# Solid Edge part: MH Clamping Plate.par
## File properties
Author: Dan
Template: metric part.par
Last saved by: Dan
Revision: 18
Application: Solid Edge
Density: 7833.000 kg/m^3
Accuracy: 0.990
Material: Steel
Face Style: Steel
Fill Style: ANSI32(Steel)
Virtual Style: Machined steel
Coef. of Thermal Exp: 1.3e-05
Thermal Conductivity: 32.0
Specific Heat: 481.0
Modulus of Elasticity: 199947953000.0
Poisson's Ratio: 0.29
Yield Stress: 262000766.0
Ultimate Stress: 358527364.0
Elongation: 0.0
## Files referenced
..\Moving Half.asm
C:\Drawing Files Other\Dave\Tente\HUP 125X36H45-TSA 02-07-2011\Wheel Mould\MH Die Plate.par
ZC:\Drawing Files Other\Dave\Tente\HUP 125X36H45-TSA 02-07-2011\Wheel Mould\Moving Half.asm
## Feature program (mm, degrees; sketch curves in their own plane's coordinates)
sketch for "unnamed Protrusion 1" plane through (0, 0, 0) normal (0, 0, 1) x-axis (1, 0, 0)
extrude "unnamed Protrusion 1" add finite 26 along -normal
sketch for "Hole_9" plane through (0, 0, -26) normal (0, 0, -1) x-axis (1, 0, 0)
  hole centre (-170, 116) bore radius 8.25
hole "Hole_9" diameter 16.5 through  CounterBoreDepth = 17 mm
sketch for "unnamed Hole 1" plane through (0, 0, -26) normal (0, 0, -1) x-axis (1, 0, 0)
hole "unnamed Hole 1" through
sketch for "unnamed Hole 2" plane through (0, 0, -26) normal (0, 0, -1) x-axis (1, 0, 0)
  hole centre (170, -116) bore radius 8.25
hole "unnamed Hole 2" through
sketch for "unnamed Hole 3" plane through (0, 0, -26) normal (0, 0, -1) x-axis (1, 0, 0)
hole "unnamed Hole 3" through
pattern "unnamed Pattern 1" of "Hole_9", "unnamed Hole 1", "unnamed Hole 2", "unnamed Hole 3"
sketch for "Hole_13" plane through (0, 0, -26) normal (0, 0, -1) x-axis (1, 0, 0)
hole "Hole_13" diameter 30 through  VBottomAngle = 118 deg
sketch for "Hole_14" plane through (0, 0, -26) normal (0, 0, -1) x-axis (-1, 0, 0)
hole "Hole_14" diameter 12.5 through  CounterBoreDepth = 12.5 mm
sketch for "unnamed Hole 4" plane through (0, 0, -26) normal (0, 0, -1) x-axis (-1, 0, 0)
hole "unnamed Hole 4" through
sketch for "unnamed Hole 5" plane through (0, 0, -26) normal (0, 0, -1) x-axis (-1, 0, 0)
  hole centre (-170, -139) bore radius 6.25
hole "unnamed Hole 5" through
sketch for "unnamed Hole 6" plane through (0, 0, -26) normal (0, 0, -1) x-axis (-1, 0, 0)
  hole centre (169.9431, -139) bore radius 6.25
hole "unnamed Hole 6" through
sketch for "unnamed Hole 7" plane through (0, 0, -26) normal (0, 0, -1) x-axis (-1, 0, 0)
  hole centre (169.9431, 0) bore radius 6.25
hole "unnamed Hole 7" through
sketch for "unnamed Hole 8" plane through (0, 0, -26) normal (0, 0, -1) x-axis (-1, 0, 0)
  hole centre (169.9431, 139) bore radius 6.25
hole "unnamed Hole 8" through
pattern "unnamed Pattern 2" of "Hole_14", "unnamed Hole 4", "unnamed Hole 5", "unnamed Hole 6", "unnamed Hole 7", "unnamed Hole 8"
sketch for "ExtrudedCutout_2" #1 plane through (0, 0, 0) normal (0, 0, 1) x-axis (-1, 0, 0)
sketch for "ExtrudedCutout_2" #2 plane through (0, 0, 0) normal (0, 0, 1) x-axis (-1, 0, 0)
sketch for "ExtrudedCutout_2" #3 plane through (0, 0, 0) normal (0, 0, 1) x-axis (-1, 0, 0)
sketch for "ExtrudedCutout_2" #4 plane through (0, 0, 0) normal (0, 0, 1) x-axis (-1, 0, 0)
  circle centre (75, 75) radius 22.25
extrude "ExtrudedCutout_2" cut finite 5 along -normal
sketch for "Hole_22" plane through (0, 0, -26) normal (0, 0, -1) x-axis (1, 0, 0)
  hole centre (-75, -94) bore radius 2.25
hole "Hole_22" diameter 4.5 through  CounterBoreDepth = 4.5 mm
sketch for "unnamed Hole 9" plane through (0, 0, -26) normal (0, 0, -1) x-axis (1, 0, 0)
  hole centre (-75, -56) bore radius 2.25
hole "unnamed Hole 9" through
sketch for "unnamed Hole 10" plane through (0, 0, -26) normal (0, 0, -1) x-axis (1, 0, 0)
  hole centre (75, -56) bore radius 2.25
hole "unnamed Hole 10" through
sketch for "unnamed Hole 11" plane through (0, 0, -26) normal (0, 0, -1) x-axis (1, 0, 0)
  hole centre (75, -94) bore radius 2.25
hole "unnamed Hole 11" through
sketch for "unnamed Hole 12" plane through (0, 0, -26) normal (0, 0, -1) x-axis (1, 0, 0)
  hole centre (75, 56) bore radius 2.25
hole "unnamed Hole 12" through
sketch for "unnamed Hole 13" plane through (0, 0, -26) normal (0, 0, -1) x-axis (1, 0, 0)
  hole centre (75, 94) bore radius 2.25
hole "unnamed Hole 13" through
sketch for "unnamed Hole 14" plane through (0, 0, -26) normal (0, 0, -1) x-axis (1, 0, 0)
  hole centre (-75, 94) bore radius 2.25
hole "unnamed Hole 14" through
sketch for "unnamed Hole 15" plane through (0, 0, -26) normal (0, 0, -1) x-axis (1, 0, 0)
  hole centre (-75, 56) bore radius 2.25
hole "unnamed Hole 15" through
pattern "unnamed Pattern 3" of "Hole_22", "unnamed Hole 9", "unnamed Hole 10", "unnamed Hole 11", "unnamed Hole 12", "unnamed Hole 13", "unnamed Hole 14", "unnamed Hole 15"
sketch for "Hole_30" plane through (0, 0, 0) normal (1, 0, 0) x-axis (0, 1, 0)
  hole centre (75, -10) bore radius 3
hole "Hole_30" diameter 6 through  VBottomAngle = 118 deg
sketch for "unnamed Hole 16" plane through (0, 0, 0) normal (1, 0, 0) x-axis (0, 1, 0)
  hole centre (-75, -10) bore radius 3
hole "unnamed Hole 16" through
pattern "unnamed Pattern 4" of "Hole_30", "unnamed Hole 16"
sketch for "ExtrudedCutout_3" #1 plane through (0, 0, 0) normal (0, 0, 1) x-axis (1, 0, 0)
  circle centre (-75, 75) radius 9
sketch for "ExtrudedCutout_3" #2 plane through (0, 0, 0) normal (0, 0, 1) x-axis (1, 0, 0)
  circle centre (75, 75) radius 9
sketch for "ExtrudedCutout_3" #3 plane through (0, 0, 0) normal (0, 0, 1) x-axis (1, 0, 0)
  circle centre (75, -75) radius 9
sketch for "ExtrudedCutout_3" #4 plane through (0, 0, 0) normal (0, 0, 1) x-axis (1, 0, 0)
  circle centre (-75, -75) radius 9
extrude "ExtrudedCutout_3" cut finite 14 along -normal
delete holes assoc c "unnamed DeleteHolesAssocC 1"
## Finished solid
Body 1: solid body, 71 faces, 98 edges, 8 vertices.
  Faces by surface: cylinder 43, plane 28
  Edges by curve: circle 78, line 12, intersection 8
Bounding box of the edges (mm): 446.000 x 396.000 x 26.000, from (-223, -198, -26) to (223, 198, 0).
Cylindrical faces by radius (mm): R2.25 x8, R3 x6, R4 x8, R6.25 x6, R9 x4, R10 x6, R15 x1, R22.25 x4
Planar faces by outward normal: +x 1, +y 1, +z 9, -x 1, -y 1, -z 15
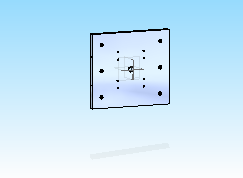
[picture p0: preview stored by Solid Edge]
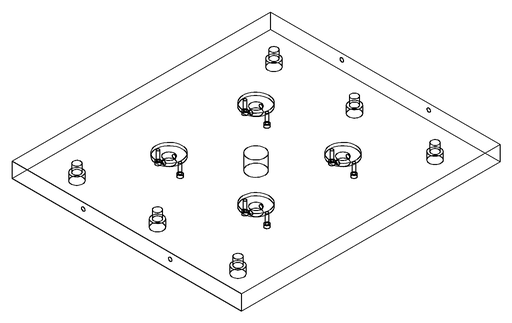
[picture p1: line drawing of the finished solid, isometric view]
